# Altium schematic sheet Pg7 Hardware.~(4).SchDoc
size 431 x 279 mm; Date: Not shown in title block; ApprovedBy: Not shown in title block; CheckedBy: Not shown in title block; Author: Not shown in title block; CompanyName: Not shown in title block; Engineer: Not shown in title block; Organization: Not shown in title block; Address1: Not shown in title block; Address2: Not shown in title block; Address3: Not shown in title block; Address4: Not shown in title block; DocumentNumber: 7; Revision: Use project parameter SCH_Rev; SheetNumber: 7; SheetTotal: 7; PageSetup: Record=PageOptions|CenterHorizontal=True|CenterVertical=True|PrintScale=1.00|XCorrection=1.00|YCorrection=1.00|PrintKind=0|BorderSize=5000000|LeftOffset=0|BottomOffset=0|Orientation=2|PaperLength=1000|PaperWidth=1000|Scale=100|PaperSource=15|PrintQuality=600|MediaType=1|DitherType=10|PaperKind=Letter|PrintScaleMode=1
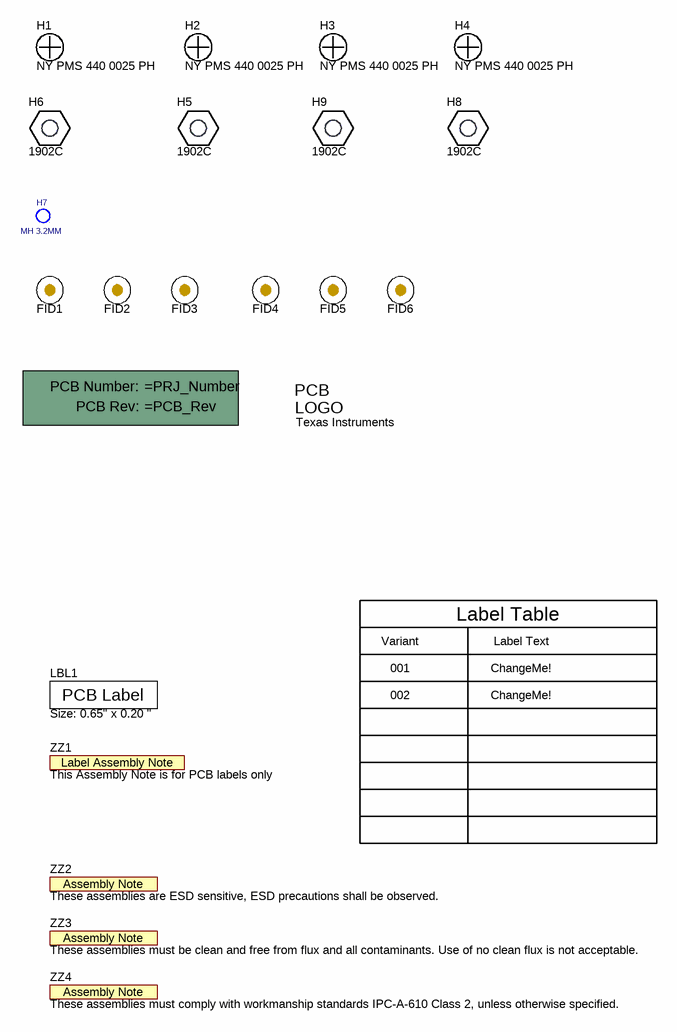
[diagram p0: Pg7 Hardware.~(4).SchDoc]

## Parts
!PCB1  Printed Circuit Board  (value not drawn)  (mechanical)
FID1  Fiducial  [Fiducial10-20]  (value not drawn)
FID2  Fiducial  [Fiducial10-20]  (value not drawn)
FID3  Fiducial  [Fiducial10-20]  (value not drawn)
FID4  Fiducial  [Fiducial10-20]  (value not drawn)
FID5  Fiducial  [Fiducial10-20]  (value not drawn)
FID6  Fiducial  [Fiducial10-20]  (value not drawn)
H1  NY PMS 440 0025 PH  [NY PMS 440 0025 PH]
H2  NY PMS 440 0025 PH  [NY PMS 440 0025 PH]
H3  NY PMS 440 0025 PH  [NY PMS 440 0025 PH]
H4  NY PMS 440 0025 PH  [NY PMS 440 0025 PH]
H5  1902C  [Keystone_1902C]
H6  1902C  [Keystone_1902C]
H7  MH 3.2MM  [MH3.2_H5_W6_KO8_STARHEAD]
H8  1902C  [Keystone_1902C]
H9  1902C  [Keystone_1902C]
LBL1  Size: 0.65" x 0.20 "  [Label_650x200]
Logo1  Texas Instruments  [TI_Stacked_SolderMask_Small]  (no BOM)
ZZ1  This Assembly Note is for PCB labels only  [AssemblyNoteLabel]  (no BOM)
ZZ2  These assemblies are ESD sensitive, ESD precautions shall be observed.  [AssemblyNote]  (no BOM)
ZZ3  These assemblies must be clean and free from flux and all contaminants. Use of no clean flux is not acceptable.  [AssemblyNote]  (no BOM)
ZZ4  These assemblies must comply with workmanship standards IPC-A-610 Class 2, unless otherwise specified.  [AssemblyNote]  (no BOM)

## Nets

Not connected (* = marked no-connect by the designer): H7 1

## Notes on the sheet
- Variant
- Label Table
- Label Text
- 001
- 002
- ChangeMe!

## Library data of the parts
!PCB1 = PCB: Manufacturer: Any; SymbolCreator: a0412235
FID1-FID6 = Fiducial: Fiducial mark.  There is nothing to buy or mount.; SymbolCreator: codlsc
H1-H4 = NY PMS 440 0025 PH: Machine Screw, Round, #4-40 x 1/4, Nylon, Philips panhead; Manufacturer: B&F Fastener Supply; CompType: Hardware; SymbolCreator: codlsc; U/M: EA
H5 H6 H8 H9 = 1902C: Standoff, Hex, 0.5"L #4-40 Nylon; Manufacturer: Keystone; CompType: Hardware
H7 = MH 3_0.5MM: Mountin hole, NPTH Drill 3.2mm
LBL1 = THT-14-423-10: Thermal Transfer Printable Labels, 0.650" W x 0.200" H - 10,000 per roll; Manufacturer: Brady; SymbolCreator: a0412235; CompType: Label
Logo1 = TI_Logo: Texas Instrument Corporate Signature; SymbolCreator: codlsc
ZZ1 = AssemblyNoteLabel: SymbolCreator: a0412235
ZZ2-ZZ4 = AssemblyNote: SymbolCreator: codlsc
